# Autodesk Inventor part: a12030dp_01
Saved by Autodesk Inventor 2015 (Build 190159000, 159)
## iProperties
Created: 2022-06
Part Number: a12030dp_01
Checked By: TraceParts S.A.
Material: Générique
Catalog Web Link: www.traceparts.com
Document SubType Name: Modeling
Designer: TraceParts
Density: 1 g/cm^3
Appearance: Par défaut
Company: TraceParts S.A.
Author: TraceParts
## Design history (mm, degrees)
feature "a12030dp_01.ipt"
node "Solide1"
